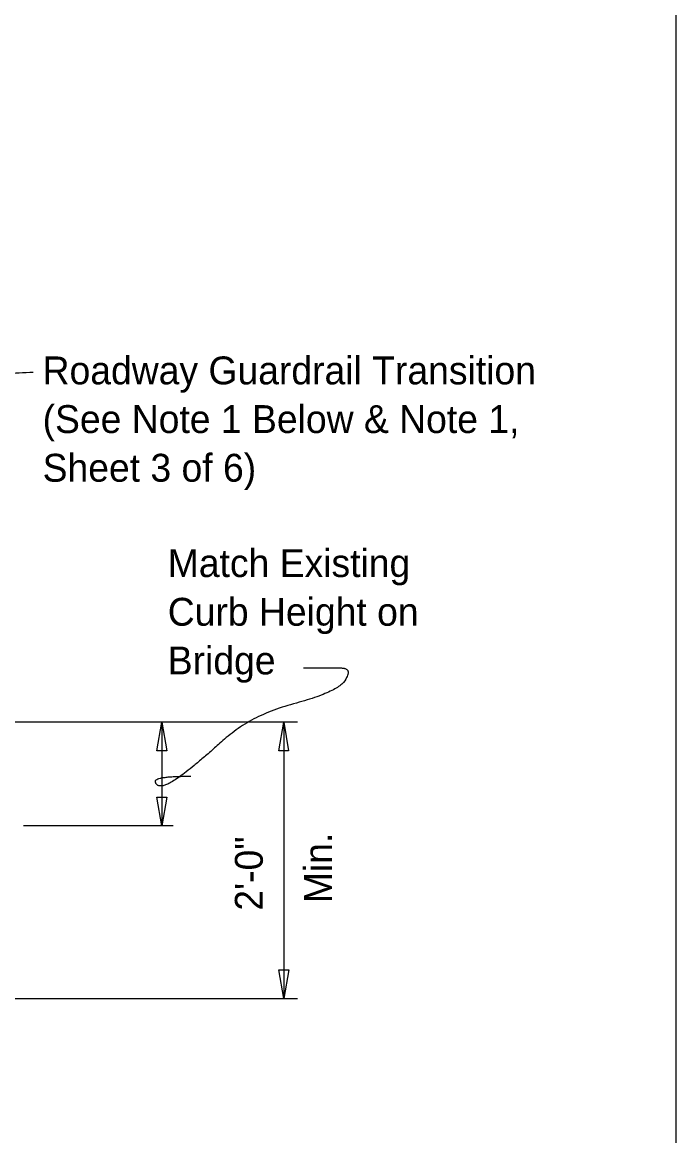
# Model space of a CAD drawing. Extents: x 1.5 to 68.7, y 0 to 31.1.
# Drawn here: x 37.81 to 42.53, y 8.74 to 16.79 of the extents above; entities that cross this region are included whole.
import ezdxf

# ---------------------------------------------------------------- set-up
doc = ezdxf.new("R2010")
doc.units = 0
for name, color, linetype in [('ActivePts-ConstElements', 7, 'Continuous'), ('Dimension', 7, 'Continuous'), ('TextStructures', 7, 'Continuous')]:
    doc.layers.add(name, color=color, linetype=linetype)

# ---------------------------------------------------------------- blocks, each defined once
blk = doc.blocks.new('Terminator-Arrow')
at = {"layer": 'Dimension'}
blk.add_lwpolyline([(0, 0), (-0.00041, 0.000069), (-0.00041, -0.000069)], close=True, dxfattribs=at)

msp = doc.modelspace()

# ---------------------------------------------------------------- linework, layer by layer
at = {"layer": 'ActivePts-ConstElements'}
msp.add_lwpolyline([(1.4667, 28.1828), (42.5333, 28.1828), (42.5333, 1.7828), (1.4667, 1.7828)], close=True, dxfattribs=at)
at = {"layer": 'Dimension'}
for p, q in [((36.8263, 11.7345), (39.8006, 11.7345)), ((38.8187, 11.7345), (38.8187, 10.9845)), ((39.7009, 11.7346), (39.7009, 9.7345)), ((37.8188, 10.9845), (38.9014, 10.9845)), ((36.8263, 9.7345), (39.8006, 9.7345))]:
    msp.add_line(p, q, dxfattribs=at)
for points in [[(37.8896, 14.2621), (37.3828, 14.2426), (37.3496, 14.1481), (37.4003, 13.5697)], [(39.8438, 12.1246), (40.0362, 12.1246), (40.1965, 12.1246), (40.0939, 11.9514), (39.4654, 11.7846), (39.0742, 11.4317), (38.8561, 11.2713), (38.7727, 11.2713), (38.7727, 11.3419), (39.0293, 11.3419)]]:
    msp.add_open_spline(points, degree=2, dxfattribs=at)

# ---------------------------------------------------------------- block references
at = {"layer": 'Dimension', "xscale": 506.349, "yscale": -512.1577380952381}
for p, rotation in [((38.8184, 11.7339), 90), ((39.7, 11.734), 90), ((38.8184, 10.984), -90), ((39.7007, 9.7344), -90)]:
    msp.add_blockref('Terminator-Arrow', p, dxfattribs=dict(at, rotation=rotation))

# ---------------------------------------------------------------- texts
at = {"layer": 'Dimension'}
for s, p in [('Roadway Guardrail Transition', (37.957, 14.1758)), ('(See Note 1 Below & Note 1,', (37.957, 13.8238)), ('Sheet 3 of 6)', (37.957, 13.4718)), ('Match Existing ', (38.8616, 12.7823)), ('Curb Height on', (38.8616, 12.4303)), ('Bridge', (38.8616, 12.0783))]:
    msp.add_text(s, height=0.2016, dxfattribs=at).set_placement(p)
at = {"layer": 'TextStructures'}
for s, p in [('2\'-0"', (39.5485, 10.3694)), ('Min.', (40.0489, 10.4239))]:
    msp.add_text(s, height=0.2016, rotation=90, dxfattribs=at).set_placement(p)

doc.saveas('drawing.dxf')
